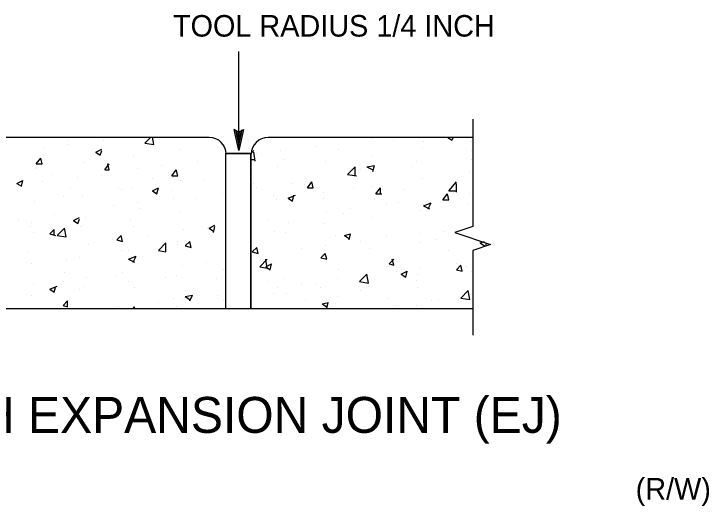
# Model space of a CAD drawing. Extents: x -118779 to -116979, y -104389 to -102939.
# Drawn here: x -118309 to -118115.4, y -103511.8 to -103374.8 of the extents above; entities that cross this region are included whole.
import ezdxf

# ---------------------------------------------------------------- set-up
doc = ezdxf.new("R2010")
doc.units = 0
for name, color, linetype in [('G-MARK', 7, 'Continuous'), ('G-TEXT', 7, 'Continuous'), ('Misc CnstDet(22)', 7, 'Continuous')]:
    doc.layers.add(name, color=color, linetype=linetype)

msp = doc.modelspace()

# ---------------------------------------------------------------- linework, layer by layer
at = {"layer": 'G-MARK'}
msp.add_line((-118246.37, -103412.82), (-118246.37, -103385.24), dxfattribs=at)
at = {"layer": 'G-TEXT'}
msp.add_lwpolyline([(-118245.05, -103406.92), (-118246.37, -103412.82), (-118247.68, -103406.92), (-118247.33, -103407.13), (-118246.37, -103411.45), (-118245.4, -103407.13), (-118245.75, -103407.33), (-118246.37, -103410.1), (-118246.98, -103407.34), (-118246.63, -103407.55), (-118246.37, -103408.74), (-118246.1, -103407.54), (-118246.37, -103407.71), (-118247.68, -103406.92), (-118246.37, -103407.71)], close=True, dxfattribs=at)
at = {"layer": 'Misc CnstDet(22)'}
for p, q in [((-118329.32, -103409.09), (-118254.66, -103409.09)), ((-118302.78, -103409.09), (-118302.78, -103409.09)), ((-118272.5, -103410.75), (-118270.84, -103409.09)), ((-118270.01, -103411.16), (-118270.43, -103409.09)), ((-118238.07, -103409.09), (-118181.25, -103409.09)), ((-118207.8, -103409.09), (-118207.8, -103409.09)), ((-118188.3, -103409.09), (-118187.06, -103409.92)), ((-118187.06, -103409.92), (-118186.64, -103409.09)), ((-118294.07, -103409.92), (-118294.07, -103409.92)), ((-118294.07, -103411.16), (-118294.07, -103411.16)), ((-118284.11, -103409.92), (-118284.11, -103409.92)), ((-118272.5, -103410.75), (-118270.01, -103411.16)), ((-118209.04, -103409.51), (-118209.04, -103409.51)), ((-118203.23, -103409.92), (-118203.23, -103409.92)), ((-118194.94, -103410.33), (-118194.94, -103410.33)), ((-118181.67, -103410.33), (-118181.67, -103410.33)), ((-118300.7, -103411.99), (-118300.7, -103411.99)), ((-118286.19, -103413.24), (-118284.53, -103412.41)), ((-118284.94, -103414.07), (-118284.53, -103412.82)), ((-118262.54, -103412.41), (-118262.54, -103412.41)), ((-118243.05, -103413.65), (-118242.22, -103412.82)), ((-118234.76, -103412.82), (-118234.76, -103412.82)), ((-118224.8, -103411.58), (-118224.8, -103411.58)), ((-118218.58, -103412.41), (-118218.58, -103412.41)), ((-118195.35, -103411.99), (-118195.35, -103411.99)), ((-118181.67, -103412.82), (-118181.67, -103412.82)), ((-118302.78, -103416.56), (-118301.53, -103414.9)), ((-118301.12, -103416.56), (-118301.53, -103414.9)), ((-118286.19, -103413.24), (-118284.94, -103414.07)), ((-118275.82, -103414.48), (-118275.82, -103414.48)), ((-118250.1, -103413.65), (-118250.1, -103456.79)), ((-118250.1, -103413.65), (-118243.05, -103413.65)), ((-118243.05, -103413.65), (-118243.05, -103456.79)), ((-118241.81, -103415.73), (-118242.22, -103413.24)), ((-118241.39, -103413.65), (-118241.39, -103413.65)), ((-118209.04, -103414.07), (-118209.04, -103414.07)), ((-118302.78, -103416.56), (-118301.12, -103416.56)), ((-118289.5, -103416.14), (-118289.5, -103416.14)), ((-118283.7, -103418.22), (-118282.45, -103416.56)), ((-118282.45, -103418.22), (-118282.87, -103416.56)), ((-118267.94, -103416.97), (-118267.94, -103416.97)), ((-118257.98, -103415.73), (-118257.98, -103415.73)), ((-118243.05, -103415.31), (-118241.81, -103415.31)), ((-118233.93, -103415.31), (-118233.93, -103415.31)), ((-118222.31, -103415.73), (-118222.31, -103415.73)), ((-118210.7, -103417.39), (-118208.63, -103416.97)), ((-118209.04, -103418.63), (-118208.63, -103416.97)), ((-118197.01, -103415.73), (-118197.01, -103415.73)), ((-118181.67, -103415.31), (-118181.67, -103415.31)), ((-118302.78, -103417.8), (-118302.78, -103417.8)), ((-118283.7, -103418.22), (-118282.45, -103418.22)), ((-118274.57, -103417.8), (-118274.57, -103417.8)), ((-118265.03, -103419.87), (-118263.79, -103418.22)), ((-118263.37, -103419.87), (-118263.79, -103418.22)), ((-118235.58, -103417.39), (-118235.58, -103417.39)), ((-118216.09, -103419.46), (-118214.02, -103417.39)), ((-118214.02, -103419.87), (-118214.02, -103417.39)), ((-118212.36, -103418.22), (-118212.36, -103418.22)), ((-118210.7, -103417.39), (-118209.04, -103418.22)), ((-118208.21, -103418.63), (-118208.21, -103418.63)), ((-118198.26, -103417.39), (-118198.26, -103417.39)), ((-118298.63, -103419.46), (-118298.63, -103419.46)), ((-118291.16, -103420.29), (-118291.16, -103420.29)), ((-118284.53, -103419.87), (-118284.53, -103419.87)), ((-118270.43, -103420.7), (-118270.43, -103420.7)), ((-118265.03, -103419.87), (-118263.37, -103419.87)), ((-118264.62, -103420.29), (-118264.62, -103420.29)), ((-118227.7, -103420.7), (-118227.7, -103420.7)), ((-118216.09, -103419.46), (-118213.6, -103419.87)), ((-118214.85, -103419.46), (-118214.85, -103419.46)), ((-118195.35, -103420.7), (-118195.35, -103420.7)), ((-118182.08, -103419.04), (-118182.08, -103419.04)), ((-118308.17, -103421.95), (-118306.51, -103421.12)), ((-118308.17, -103421.95), (-118306.92, -103422.78)), ((-118307.75, -103422.36), (-118307.75, -103422.36)), ((-118306.92, -103422.78), (-118306.51, -103421.12)), ((-118306.92, -103422.36), (-118306.92, -103422.36)), ((-118301.12, -103421.53), (-118301.12, -103421.53)), ((-118262.54, -103421.12), (-118262.54, -103421.12)), ((-118256.32, -103421.12), (-118256.32, -103421.12)), ((-118242.22, -103421.95), (-118242.22, -103421.95)), ((-118231.44, -103421.95), (-118231.44, -103421.95)), ((-118228.12, -103422.36), (-118228.12, -103422.36)), ((-118227.29, -103423.19), (-118226.05, -103421.53)), ((-118225.63, -103423.19), (-118226.05, -103421.53)), ((-118209.04, -103422.78), (-118209.04, -103422.78)), ((-118187.89, -103424.02), (-118185.81, -103421.53)), ((-118185.81, -103424.44), (-118185.81, -103421.95)), ((-118293.24, -103423.19), (-118293.24, -103423.19)), ((-118279.96, -103423.19), (-118279.96, -103423.19)), ((-118279.14, -103423.61), (-118279.14, -103423.61)), ((-118276.23, -103423.19), (-118276.23, -103423.19)), ((-118270.43, -103424.02), (-118268.77, -103423.19)), ((-118270.43, -103424.02), (-118269.18, -103424.85)), ((-118269.18, -103424.85), (-118268.77, -103423.19)), ((-118265.03, -103424.02), (-118265.03, -103424.02)), ((-118241.39, -103423.19), (-118241.39, -103423.19)), ((-118227.29, -103423.19), (-118225.63, -103423.19)), ((-118222.73, -103424.44), (-118222.73, -103424.44)), ((-118214.43, -103423.19), (-118214.43, -103423.19)), ((-118208.21, -103424.85), (-118206.97, -103423.19)), ((-118206.97, -103424.85), (-118206.97, -103423.19)), ((-118200.33, -103423.61), (-118200.33, -103423.61)), ((-118187.89, -103424.02), (-118185.81, -103424.02)), ((-118186.23, -103424.02), (-118186.23, -103424.02)), ((-118295.31, -103425.68), (-118295.31, -103425.68)), ((-118289.92, -103425.27), (-118289.92, -103425.27)), ((-118264.62, -103426.1), (-118264.62, -103426.1)), ((-118258.4, -103426.1), (-118258.4, -103426.1)), ((-118250.93, -103424.85), (-118250.93, -103424.85)), ((-118236.83, -103425.27), (-118236.83, -103425.27)), ((-118236, -103426.51), (-118236, -103426.51)), ((-118232.68, -103426.1), (-118230.61, -103425.27)), ((-118232.68, -103426.1), (-118231.44, -103426.93)), ((-118231.44, -103426.93), (-118231.02, -103425.27)), ((-118222.73, -103426.1), (-118222.73, -103426.1)), ((-118208.63, -103426.51), (-118208.63, -103426.51)), ((-118208.21, -103424.85), (-118206.55, -103424.85)), ((-118189.55, -103426.51), (-118188.3, -103424.85)), ((-118189.55, -103426.51), (-118187.89, -103426.51)), ((-118188.72, -103425.68), (-118188.72, -103425.68)), ((-118187.89, -103426.51), (-118188.3, -103424.85)), ((-118186.64, -103424.85), (-118186.64, -103424.85)), ((-118182.08, -103424.85), (-118182.08, -103424.85)), ((-118303.19, -103426.93), (-118303.19, -103426.93)), ((-118281.21, -103428.17), (-118281.21, -103428.17)), ((-118274.57, -103427.34), (-118274.57, -103427.34)), ((-118205.31, -103427.75), (-118205.31, -103427.75)), ((-118201.99, -103427.34), (-118201.99, -103427.34)), ((-118194.94, -103428.17), (-118192.86, -103427.34)), ((-118194.94, -103428.17), (-118193.28, -103429)), ((-118194.52, -103427.34), (-118194.52, -103427.34)), ((-118193.69, -103429), (-118192.86, -103427.34)), ((-118182.5, -103427.75), (-118182.5, -103427.75)), ((-118273.74, -103429), (-118273.74, -103429)), ((-118262.96, -103429.83), (-118262.96, -103429.83)), ((-118221.9, -103429.83), (-118221.9, -103429.83)), ((-118217.34, -103430.24), (-118217.34, -103430.24)), ((-118215.26, -103429), (-118215.26, -103429)), ((-118195.77, -103429.41), (-118195.77, -103429.41)), ((-118307.75, -103431.9), (-118307.75, -103431.9)), ((-118297.8, -103430.66), (-118297.8, -103430.66)), ((-118292.41, -103432.32), (-118290.75, -103431.49)), ((-118292.41, -103432.32), (-118291.16, -103433.15)), ((-118291.16, -103433.15), (-118290.75, -103431.9)), ((-118289.09, -103431.49), (-118289.09, -103431.49)), ((-118276.65, -103431.9), (-118276.65, -103431.9)), ((-118238.49, -103432.32), (-118238.49, -103432.32)), ((-118209.45, -103431.49), (-118209.45, -103431.49)), ((-118304.44, -103433.98), (-118304.44, -103433.98)), ((-118304.02, -103432.73), (-118304.02, -103432.73)), ((-118296.97, -103436.46), (-118294.9, -103434.39)), ((-118294.48, -103436.88), (-118294.9, -103434.39)), ((-118290.33, -103433.98), (-118290.33, -103433.98)), ((-118289.92, -103433.56), (-118289.92, -103433.56)), ((-118275.82, -103433.98), (-118275.82, -103433.98)), ((-118255.08, -103434.39), (-118255.08, -103434.39)), ((-118254.66, -103434.39), (-118253.01, -103433.56)), ((-118254.66, -103434.39), (-118253.42, -103435.22)), ((-118253.42, -103435.64), (-118253.01, -103433.98)), ((-118232.68, -103432.73), (-118232.68, -103432.73)), ((-118222.73, -103433.15), (-118222.73, -103433.15)), ((-118303.61, -103435.64), (-118303.61, -103435.64)), ((-118299.04, -103436.05), (-118297.8, -103434.81)), ((-118299.04, -103436.05), (-118297.38, -103436.46)), ((-118297.8, -103436.46), (-118297.8, -103434.81)), ((-118261.72, -103434.81), (-118261.72, -103434.81)), ((-118236.41, -103435.22), (-118236.41, -103435.22)), ((-118233.51, -103435.64), (-118233.51, -103435.64)), ((-118216.92, -103436.46), (-118215.26, -103436.05)), ((-118215.68, -103437.71), (-118215.26, -103436.05)), ((-118195.77, -103436.05), (-118195.77, -103436.05)), ((-118189.13, -103435.22), (-118189.13, -103435.22)), ((-118296.97, -103436.46), (-118294.48, -103436.88)), ((-118281.62, -103437.71), (-118281.62, -103437.71)), ((-118280.38, -103437.71), (-118279.14, -103436.46)), ((-118280.38, -103437.71), (-118278.72, -103438.12)), ((-118278.72, -103438.12), (-118279.14, -103436.46)), ((-118271.67, -103436.46), (-118271.67, -103436.46)), ((-118263.37, -103438.12), (-118263.37, -103438.12)), ((-118261.3, -103439.37), (-118260.06, -103438.12)), ((-118259.64, -103439.78), (-118260.06, -103438.12)), ((-118250.1, -103437.29), (-118250.1, -103437.29)), ((-118219.41, -103436.46), (-118219.41, -103436.46)), ((-118216.92, -103436.46), (-118215.68, -103437.29)), ((-118212.36, -103438.12), (-118212.36, -103438.12)), ((-118205.31, -103436.88), (-118205.31, -103436.88)), ((-118191.21, -103437.71), (-118191.21, -103437.71)), ((-118179.18, -103438.54), (-118177.93, -103438.12)), ((-118288.26, -103438.95), (-118288.26, -103438.95)), ((-118268.77, -103440.61), (-118266.69, -103438.54)), ((-118266.69, -103441.03), (-118266.69, -103438.54)), ((-118263.37, -103438.95), (-118263.37, -103438.95)), ((-118261.3, -103439.37), (-118259.64, -103439.78)), ((-118242.64, -103441.03), (-118241.39, -103439.78)), ((-118240.98, -103441.44), (-118241.39, -103439.78)), ((-118228.95, -103440.2), (-118228.95, -103440.2)), ((-118222.31, -103439.37), (-118222.31, -103439.37)), ((-118209.87, -103440.2), (-118209.87, -103440.2)), ((-118196.18, -103438.54), (-118196.18, -103438.54)), ((-118179.18, -103438.54), (-118177.93, -103439.37)), ((-118177.52, -103439.37), (-118177.52, -103438.54)), ((-118304.85, -103441.03), (-118304.85, -103441.03)), ((-118279.14, -103440.61), (-118279.14, -103440.61)), ((-118277.06, -103440.61), (-118277.06, -103440.61)), ((-118268.77, -103440.61), (-118266.69, -103441.03)), ((-118242.64, -103441.03), (-118240.98, -103441.44)), ((-118223.56, -103442.69), (-118222.31, -103441.44)), ((-118223.14, -103441.86), (-118223.14, -103441.86)), ((-118221.9, -103443.1), (-118222.31, -103441.44)), ((-118187.89, -103440.61), (-118187.89, -103440.61)), ((-118294.48, -103443.52), (-118294.48, -103443.52)), ((-118290.75, -103442.69), (-118290.75, -103442.69)), ((-118277.06, -103443.1), (-118274.99, -103442.27)), ((-118277.06, -103443.1), (-118275.4, -103443.93)), ((-118275.82, -103443.93), (-118274.99, -103442.27)), ((-118255.49, -103443.93), (-118255.49, -103443.93)), ((-118240.56, -103445.17), (-118238.49, -103443.1)), ((-118238.49, -103445.59), (-118238.9, -103443.1)), ((-118236.83, -103443.93), (-118236.83, -103443.93)), ((-118223.56, -103442.69), (-118221.9, -103443.1)), ((-118204.48, -103444.35), (-118203.23, -103443.1)), ((-118203.23, -103444.76), (-118203.65, -103443.1)), ((-118203.23, -103443.1), (-118203.23, -103443.1)), ((-118304.02, -103444.35), (-118304.02, -103444.35)), ((-118262.13, -103444.76), (-118262.13, -103444.76)), ((-118250.52, -103446), (-118250.52, -103446)), ((-118240.56, -103445.17), (-118238.49, -103445.59)), ((-118238.9, -103445.17), (-118237.24, -103444.35)), ((-118238.9, -103445.17), (-118237.66, -103446)), ((-118237.66, -103446), (-118237.24, -103444.35)), ((-118218.58, -103446), (-118218.58, -103446)), ((-118204.48, -103444.35), (-118203.23, -103444.76)), ((-118195.77, -103445.59), (-118195.77, -103445.59)), ((-118185.81, -103444.35), (-118185.81, -103444.35)), ((-118185.81, -103446), (-118184.57, -103444.76)), ((-118185.81, -103446), (-118184.15, -103446.42)), ((-118184.15, -103446.42), (-118184.57, -103444.76)), ((-118182.91, -103445.17), (-118182.91, -103445.17)), ((-118294.9, -103446.83), (-118294.9, -103446.83)), ((-118280.79, -103447.66), (-118280.79, -103447.66)), ((-118278.72, -103446.83), (-118278.72, -103446.83)), ((-118263.79, -103447.66), (-118263.79, -103447.66)), ((-118212.77, -103449.32), (-118210.7, -103447.25)), ((-118210.28, -103449.74), (-118210.7, -103447.25)), ((-118202.4, -103446.42), (-118202.4, -103446.42)), ((-118201.16, -103447.25), (-118199.5, -103446.42)), ((-118201.16, -103447.25), (-118199.92, -103448.08)), ((-118199.92, -103448.08), (-118199.5, -103446.42)), ((-118196.6, -103447.25), (-118196.6, -103447.25)), ((-118181.67, -103446.42), (-118181.67, -103446.42)), ((-118303.61, -103449.74), (-118303.61, -103449.74)), ((-118295.31, -103449.32), (-118295.31, -103449.32)), ((-118288.67, -103448.08), (-118288.67, -103448.08)), ((-118277.06, -103449.32), (-118277.06, -103449.32)), ((-118266.69, -103448.08), (-118266.69, -103448.08)), ((-118252.59, -103448.49), (-118252.59, -103448.49)), ((-118238.49, -103449.32), (-118238.49, -103449.32)), ((-118233.93, -103448.49), (-118233.93, -103448.49)), ((-118228.95, -103449.74), (-118228.95, -103449.74)), ((-118224.8, -103449.74), (-118224.8, -103449.74)), ((-118218.99, -103448.49), (-118218.99, -103448.49)), ((-118212.77, -103449.32), (-118210.28, -103449.74)), ((-118210.28, -103449.32), (-118210.28, -103449.32)), ((-118197.01, -103448.91), (-118197.01, -103448.91)), ((-118299.04, -103451.4), (-118296.97, -103450.57)), ((-118299.04, -103451.4), (-118297.8, -103452.23)), ((-118297.8, -103452.23), (-118297.38, -103450.98)), ((-118290.75, -103451.4), (-118290.75, -103451.4)), ((-118289.5, -103450.57), (-118289.5, -103450.57)), ((-118275.4, -103450.98), (-118275.4, -103450.98)), ((-118261.3, -103451.81), (-118261.3, -103451.81)), ((-118235.58, -103450.98), (-118235.58, -103450.98)), ((-118223.56, -103450.98), (-118223.56, -103450.98)), ((-118212.36, -103451.81), (-118212.36, -103451.81)), ((-118210.7, -103450.57), (-118210.7, -103450.57)), ((-118196.6, -103450.98), (-118196.6, -103450.98)), ((-118184.57, -103453.88), (-118182.5, -103451.81)), ((-118182.5, -103451.81), (-118182.5, -103451.81)), ((-118182.08, -103454.3), (-118182.5, -103451.81)), ((-118304.02, -103453.06), (-118304.02, -103453.06)), ((-118261.3, -103453.47), (-118259.23, -103453.06)), ((-118261.3, -103453.47), (-118260.06, -103454.3)), ((-118260.06, -103454.71), (-118259.23, -103453.06)), ((-118252.18, -103453.06), (-118252.18, -103453.06)), ((-118236.83, -103452.64), (-118236.83, -103452.64)), ((-118233.1, -103452.64), (-118233.1, -103452.64)), ((-118218.99, -103453.47), (-118218.99, -103453.47)), ((-118295.31, -103455.96), (-118294.07, -103454.71)), ((-118294.07, -103456.37), (-118294.07, -103454.71)), ((-118268.77, -103455.13), (-118268.77, -103455.13)), ((-118264.62, -103453.88), (-118264.62, -103453.88)), ((-118262.13, -103454.3), (-118262.13, -103454.3)), ((-118250.52, -103454.71), (-118250.52, -103454.71)), ((-118227.7, -103454.3), (-118227.7, -103454.3)), ((-118223.14, -103455.54), (-118221.48, -103455.13)), ((-118223.14, -103455.54), (-118221.9, -103456.37)), ((-118221.9, -103456.79), (-118221.48, -103455.13)), ((-118204.89, -103453.88), (-118204.89, -103453.88)), ((-118192.86, -103454.71), (-118192.86, -103454.71)), ((-118190.79, -103454.71), (-118190.79, -103454.71)), ((-118184.57, -103453.88), (-118182.08, -103454.3)), ((-118183.32, -103453.88), (-118183.32, -103453.88)), ((-118329.32, -103456.79), (-118181.25, -103456.79)), ((-118295.31, -103455.96), (-118294.07, -103456.37)), ((-118279.96, -103456.37), (-118279.96, -103456.37)), ((-118275.82, -103456.79), (-118275.4, -103456.37)), ((-118275.4, -103456.79), (-118275.4, -103456.37)), ((-118263.79, -103456.37), (-118263.79, -103456.37)), ((-118209.45, -103456.79), (-118209.45, -103456.79)), ((-118202.82, -103455.96), (-118202.82, -103455.96)), ((-118197.01, -103455.96), (-118197.01, -103455.96))]:
    msp.add_line(p, q, dxfattribs=at)
for points in [[(-118181.25, -103404.11), (-118181.25, -103433.98), (-118186.23, -103435.64), (-118176.27, -103438.95), (-118181.25, -103440.61), (-118181.25, -103464.25)], [(-118243.05, -103413.65), (-118250.1, -103413.65), (-118250.1, -103456.79), (-118243.05, -103456.79), (-118243.05, -103413.65)]]:
    msp.add_lwpolyline(points, dxfattribs=at)
for centre, start, end in [((-118254.6, -103413.84), 0, 90), ((-118238.23, -103413.84), 90, 180)]:
    msp.add_arc(centre, 4.68, start, end, dxfattribs=at)

# ---------------------------------------------------------------- texts
for s, height, p in [('TOOL RADIUS 1/4 INCH', 6, (-118264.71, -103381.08)), ('1/2 INCH EXPANSION JOINT (EJ)', 10, (-118363.76, -103491.43)), ('(R/W)', 6, (-118135.88, -103510.02))]:
    msp.add_text(s, height=height, dxfattribs=at).set_placement(p)

doc.saveas('drawing.dxf')
